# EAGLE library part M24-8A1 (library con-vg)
CONNECTOR male, 24 pins + 8 high current, type C, rows ABC, grid 2.54 mm
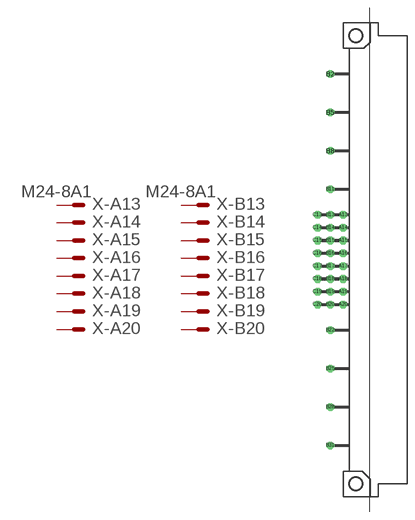
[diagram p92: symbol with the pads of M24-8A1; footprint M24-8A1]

Designator prefix X; gates -A13=MVAL -A14=MAL -A15=MAL -A16=MAL -A17=MAL -A18=MAL -A19=MAL -A20=MAL -B13=MVAL -B14=MAL -B15=MAL -B16=MAL -B17=MAL -B18=MAL -B19=MAL -B20=MAL -C13=MVAL -C14=MAL -C15=MAL -C16=MAL -C17=MAL -C18=MAL -C19=MAL -C20=MAL -1=MAL-HIGHCUR -2=MAL-HIGHCUR -3=MAL-HIGHCUR -4=MAL-HIGHCUR -5=MAL-HIGHCUR -6=MAL-HIGHCUR -7=MAL-HIGHCUR -8=MAL-HIGHCUR

## M24-8A1  [M24-8A1]
A13  -A13:S  pas
A14  -A14:S  pas
A15  -A15:S  pas
A16  -A16:S  pas
A17  -A17:S  pas
A18  -A18:S  pas
A19  -A19:S  pas
A20  -A20:S  pas
B2  -1:B  pas
B5  -2:B  pas
B8  -3:B  pas
B11  -4:B  pas
B13  -B13:S  pas
B14  -B14:S  pas
B15  -B15:S  pas
B16  -B16:S  pas
B17  -B17:S  pas
B18  -B18:S  pas
B19  -B19:S  pas
B20  -B20:S  pas
B22  -5:B  pas
B25  -6:B  pas
B28  -7:B  pas
B31  -8:B  pas
C13  -C13:S  pas
C14  -C14:S  pas
C15  -C15:S  pas
C16  -C16:S  pas
C17  -C17:S  pas
C18  -C18:S  pas
C19  -C19:S  pas
C20  -C20:S  pas

## Footprint M24-8A1 (pad centres in mm)
CONNECTOR male, 24 pins + 8 high current, type C, rows ABC, grid 2.54 mm
drill 1.016 octagon: A13 -2.54,8.89; A14 -2.54,6.35; A15 -2.54,3.81; A16 -2.54,1.27; A17 -2.54,-1.27; A18 -2.54,-3.81; A19 -2.54,-6.35; A20 -2.54,-8.89; B2 -5.08,36.83; B5 -5.08,29.21; B8 -5.08,21.59; B11 -5.08,13.97; B13 -5.08,8.89; B14 -5.08,6.35; B15 -5.08,3.81; B16 -5.08,1.27; B17 -5.08,-1.27; B18 -5.08,-3.81; B19 -5.08,-6.35; B20 -5.08,-8.89; B22 -5.08,-13.97; B25 -5.08,-21.59; B28 -5.08,-29.21; B31 -5.08,-36.83; C13 -7.62,8.89; C14 -7.62,6.35; C15 -7.62,3.81; C16 -7.62,1.27; C17 -7.62,-1.27; C18 -7.62,-3.81; C19 -7.62,-6.35; C20 -7.62,-8.89
hole 2.8 at 0,44.45
hole 2.8 at 0,-44.45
